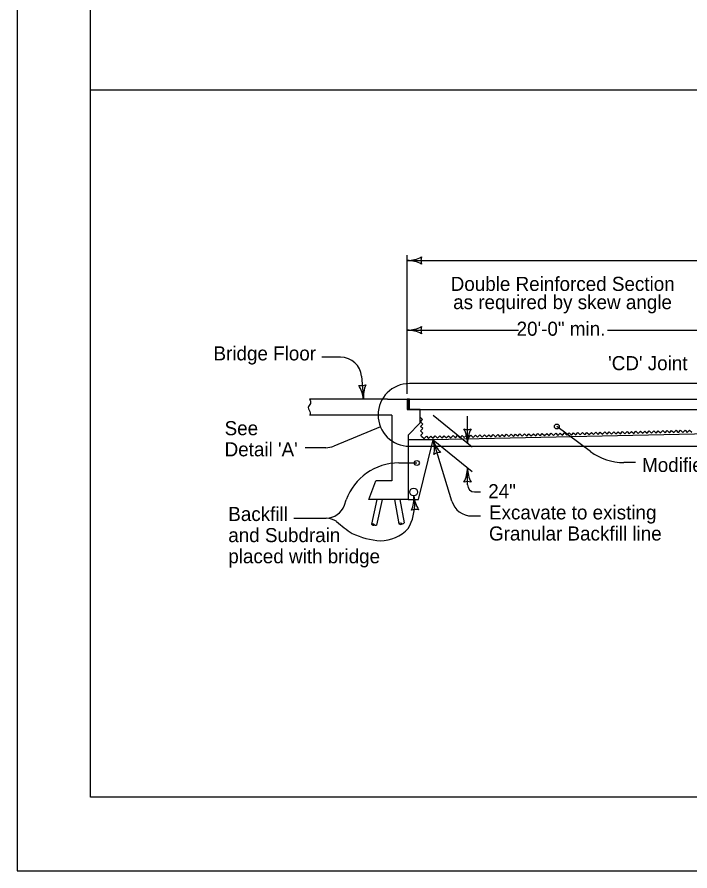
# Model space of a CAD drawing. Extents: x -2135039 to -2120895, y -2139150 to -2136566.
# Drawn here: x -2127839 to -2126883, y -2139150 to -2137937 of the extents above; entities that cross this region are included whole.
import ezdxf

# ---------------------------------------------------------------- set-up
doc = ezdxf.new("R2010")
doc.units = 0
for name, color, linetype in [('dsnDOTLogo', 7, 'Continuous'), ('dsnNonPlotable', 7, 'Continuous'), ('dsnStdDimension', 7, 'Continuous'), ('dsnStdLabel', 7, 'Continuous'), ('dsnStdLineWork', 7, 'Continuous'), ('Level 1', 7, 'Continuous'), ('Level 2', 7, 'Continuous'), ('Level 3', 7, 'Continuous')]:
    doc.layers.add(name, color=color, linetype=linetype)

msp = doc.modelspace()

# ---------------------------------------------------------------- linework, layer by layer
at = {"layer": 'dsnDOTLogo'}
msp.add_lwpolyline([(-2127839, -2139150.4), (-2124495, -2139150.4), (-2124495, -2136566.4), (-2127839, -2136566.4)], close=True, dxfattribs=at)
at = {"layer": 'dsnNonPlotable'}
msp.add_line((-2127734.5, -2138040.9), (-2124599.5, -2138040.9), dxfattribs=at)
at = {"layer": 'dsnStdDimension'}
for p, q in [((-2127248, -2138502.9), (-2127192.8, -2138548)), ((-2127199.2, -2138542.7), (-2127199.2, -2138504.5)), ((-2127248, -2138538.2), (-2127192.8, -2138583.2)), ((-2127199.2, -2138602), (-2127199.2, -2138578)), ((-2127189.2, -2138612), (-2127180.7, -2138612))]:
    msp.add_line(p, q, dxfattribs=at)
for centre, radius, start, end in [((-2127199.2, -2138506.9), 16.5, 252.2666, 287.7333), ((-2127242, -2138542.7), 42.7, 360, 28.0725), ((-2127156.5, -2138542.7), 42.7, 151.9275, 180), ((-2127242, -2138578), 42.7, 331.9275, 360), ((-2127156.5, -2138578), 42.7, 180, 208.0725), ((-2127199.2, -2138613.8), 16.5, 72.2666, 107.7334)]:
    msp.add_arc(centre, radius, start, end, dxfattribs=at)
at = {"layer": 'dsnStdLabel'}
for p, q in [((-2127284.7, -2138472.9), (-2127284.7, -2138275.9)), ((-2127284.7, -2138283.3), (-2126123.4, -2138283.3)), ((-2127284.7, -2138382.3), (-2127126.9, -2138382.3)), ((-2127000.6, -2138382.3), (-2126836.2, -2138382.3)), ((-2127379.4, -2138420.7), (-2127406.1, -2138420.7)), ((-2127349.8, -2138447.8), (-2127347, -2138480.3)), ((-2126476.6, -2138458), (-2127281.7, -2138458)), ((-2127322.9, -2138519.6), (-2127389, -2138547)), ((-2127024.4, -2138554.7), (-2127072.4, -2138519.1)), ((-2127400.4, -2138549.2), (-2127429.6, -2138549.2)), ((-2127281.7, -2138547.1), (-2126476.6, -2138547.1)), ((-2127221.6, -2138625.1), (-2127248, -2138538.2)), ((-2127296.9, -2138570.9), (-2127271.1, -2138570.9)), ((-2126960.4, -2138570.3), (-2126977.2, -2138570.3)), ((-2127374.1, -2138631), (-2127371.4, -2138623.4)), ((-2127193.1, -2138646.2), (-2127180.7, -2138646.2)), ((-2127445.9, -2138649.4), (-2127400.2, -2138649.4))]:
    msp.add_line(p, q, dxfattribs=at)
for centre in [(-2127072.4, -2138519.1), (-2127271.1, -2138570.9)]:
    msp.add_circle(centre, 3.46, dxfattribs=at)
for centre, radius, start, end in [((-2127284.7, -2138240.5), 42.7, 270, 298.0725), ((-2127248.8, -2138283.3), 16.5, 162.2666, 197.7334), ((-2127284.7, -2138326), 42.7, 61.9275, 90), ((-2127284.7, -2138339.5), 42.7, 270, 298.0725), ((-2127248.8, -2138382.3), 16.5, 162.2666, 197.7334), ((-2127284.7, -2138425), 42.7, 61.9275, 90), ((-2127379.4, -2138450.4), 29.7, 4.9696, 90), ((-2127350.1, -2138444.6), 16.5, 257.2356, 292.7023), ((-2127389.6, -2138484), 42.7, 4.969, 33.0415), ((-2127304.4, -2138476.6), 42.7, 156.8965, 184.969), ((-2127281.7, -2138502.6), 44.5, 90, 269.9998), ((-2127400.4, -2138519.5), 29.7, 270, 292.4496), ((-2127207.2, -2138525.8), 42.7, 196.9537, 225.0262), ((-2127288.9, -2138550.7), 42.7, 348.8812, 16.9537), ((-2127207.2, -2138525.8), 42.7, 196.9537, 225.0262), ((-2127288.9, -2138550.7), 42.7, 348.8812, 16.9537), ((-2127237.6, -2138572.5), 16.5, 89.2203, 124.687), ((-2127237.6, -2138572.5), 16.5, 89.2203, 124.687), ((-2126977.2, -2138491.1), 79.2, 233.4243, 270), ((-2127296.9, -2138650.1), 79.2, 90, 160.3012), ((-2127317.8, -2138621.6), 42.5, 337.1139, 5.1864), ((-2127233.1, -2138614), 42.5, 185.1864, 213.2589), ((-2127400.2, -2138621.7), 27.7, 270, 340.3019), ((-2127345.5, -2138629), 71.3, 330.5092, 2.0511), ((-2127193.2, -2138616.5), 29.7, 196.9535, 270), ((-2127272.2, -2138653.3), 16.4, 77.453, 112.9197), ((-2127400.2, -2138677.1), 27.7, 56.8248, 90), ((-2127273.8, -2138534), 163.6, 227.1442, 236.9942), ((-2127323.5, -2138626.4), 55, 270.3325, 316.7198), ((-2127313.9, -2138563.3), 118.5, 245.5915, 265.546)]:
    msp.add_arc(centre, radius, start, end, dxfattribs=at)
at = {"layer": 'dsnStdLineWork'}
for p, q in [((-2127312.9, -2138480.3), (-2127423.5, -2138480.3)), ((-2127312.9, -2138480.3), (-2127284.7, -2138480.3)), ((-2127284.7, -2138480.3), (-2127284.7, -2138495.1)), ((-2127281.7, -2138480.3), (-2127284.7, -2138480.3)), ((-2127284.7, -2138483.7), (-2127281.7, -2138480.7)), ((-2127284.7, -2138481.6), (-2127283.8, -2138480.7)), ((-2127281.7, -2138480.7), (-2127284.7, -2138480.7)), ((-2127284.7, -2138485.8), (-2127281.7, -2138482.8)), ((-2127284.7, -2138487.9), (-2127281.7, -2138484.9)), ((-2127284.7, -2138490), (-2127281.7, -2138487)), ((-2127281.7, -2138480.3), (-2126123.4, -2138480.3)), ((-2127284.7, -2138492.1), (-2127281.7, -2138489.1)), ((-2127284.7, -2138494.2), (-2127281.7, -2138491.2)), ((-2127284.7, -2138495.1), (-2127281.7, -2138495.1)), ((-2127283.5, -2138495.1), (-2127281.7, -2138493.3)), ((-2126123.4, -2138495.2), (-2127281.7, -2138495.2)), ((-2127266.8, -2138495.1), (-2127266.8, -2138514.5)), ((-2127306.9, -2138503.2), (-2127423.5, -2138503.2)), ((-2127306.9, -2138503.2), (-2127306.9, -2138596.1)), ((-2126123.4, -2138512.8), (-2127248, -2138538.2)), ((-2127266.8, -2138514.5), (-2127283.6, -2138531.3)), ((-2127283.6, -2138531.3), (-2127283.6, -2138622.9)), ((-2127248, -2138538.2), (-2127283.6, -2138538.2)), ((-2127268.7, -2138622.9), (-2127248, -2138538.2)), ((-2127339.6, -2138622.9), (-2127329.3, -2138596.1)), ((-2127306.9, -2138596.1), (-2127329.3, -2138596.1)), ((-2127283.6, -2138622.9), (-2127339.6, -2138622.9)), ((-2127328.1, -2138622.9), (-2127335.6, -2138657.7)), ((-2127320.5, -2138622.9), (-2127328.4, -2138659.3)), ((-2127302.9, -2138622.9), (-2127296.6, -2138657.2)), ((-2127295.3, -2138622.9), (-2127289.3, -2138655.9)), ((-2127283.6, -2138622.9), (-2127268.7, -2138622.9))]:
    msp.add_line(p, q, dxfattribs=at)
for points in [[(-2127263.9, -2138533.3), (-2127265.6, -2138531.6), (-2127262.5, -2138528.4), (-2127265.8, -2138525.3), (-2127262.7, -2138522.1), (-2127265.9, -2138519), (-2127262.8, -2138515.7), (-2127266, -2138512.6), (-2127263, -2138509.4), (-2127266.2, -2138506.3), (-2127266, -2138506.1)], [(-2126977.4, -2138527.9), (-2126975.7, -2138529.4), (-2126972.6, -2138526.2), (-2126969.4, -2138529.3), (-2126966.3, -2138526), (-2126963.1, -2138529.1), (-2126960, -2138525.9), (-2126956.7, -2138529), (-2126953.6, -2138525.7), (-2126950.4, -2138528.8), (-2126947.3, -2138525.6), (-2126944.1, -2138528.7), (-2126941, -2138525.4), (-2126937.7, -2138528.5), (-2126934.6, -2138525.3), (-2126931.4, -2138528.4), (-2126928.3, -2138525.1), (-2126925.1, -2138528.2), (-2126922, -2138525), (-2126918.7, -2138528.1), (-2126915.6, -2138524.8), (-2126912.4, -2138527.9), (-2126909.3, -2138524.7), (-2126906.1, -2138527.8), (-2126903, -2138524.5), (-2126901.3, -2138526.1)], [(-2126901.3, -2138526.1), (-2126899.7, -2138527.7), (-2126896.6, -2138524.4), (-2126893.4, -2138527.5), (-2126890.3, -2138524.3), (-2126887.1, -2138527.4), (-2126884, -2138524.1), (-2126880.7, -2138527.2)], [(-2127264.1, -2138533.2), (-2127264, -2138533.1), (-2127260.8, -2138536.2), (-2127257.7, -2138532.9), (-2127254.4, -2138536), (-2127251.4, -2138532.8), (-2127248.1, -2138535.9), (-2127245, -2138532.6), (-2127241.8, -2138535.7), (-2127238.7, -2138532.5), (-2127235.4, -2138535.6), (-2127232.3, -2138532.3), (-2127229.1, -2138535.4), (-2127226, -2138532.2), (-2127222.8, -2138535.3), (-2127219.7, -2138532), (-2127216.4, -2138535.1), (-2127213.3, -2138531.9), (-2127210.1, -2138535), (-2127207, -2138531.8), (-2127205.4, -2138533.3)], [(-2127205.4, -2138533.2), (-2127203.8, -2138534.8), (-2127200.7, -2138531.5), (-2127197.4, -2138534.6), (-2127194.3, -2138531.4), (-2127191.1, -2138534.5), (-2127188, -2138531.2), (-2127184.8, -2138534.3), (-2127181.7, -2138531.1), (-2127178.4, -2138534.2), (-2127175.3, -2138530.9), (-2127172.1, -2138534), (-2127169, -2138530.8), (-2127165.8, -2138533.9), (-2127162.7, -2138530.6), (-2127159.4, -2138533.7), (-2127156.3, -2138530.5), (-2127153.1, -2138533.6), (-2127150, -2138530.3), (-2127146.8, -2138533.4), (-2127143.7, -2138530.2), (-2127140.4, -2138533.3), (-2127137.3, -2138530.1), (-2127134.1, -2138533.1), (-2127131, -2138529.9), (-2127129.4, -2138531.5)], [(-2127129.4, -2138531.4), (-2127127.8, -2138533), (-2127124.7, -2138529.7), (-2127121.4, -2138532.8), (-2127118.3, -2138529.6), (-2127115.1, -2138532.7), (-2127112, -2138529.4), (-2127108.8, -2138532.5), (-2127105.7, -2138529.3), (-2127102.4, -2138532.4), (-2127099.3, -2138529.2), (-2127096.1, -2138532.2), (-2127093, -2138529), (-2127089.8, -2138532.1), (-2127086.7, -2138528.9), (-2127083.4, -2138532), (-2127080.3, -2138528.7), (-2127077.1, -2138531.8), (-2127074, -2138528.6), (-2127070.8, -2138531.7), (-2127067.7, -2138528.4), (-2127064.4, -2138531.5), (-2127061.3, -2138528.3), (-2127058.1, -2138531.4), (-2127055, -2138528.1), (-2127053.4, -2138529.7)], [(-2127053.4, -2138529.7), (-2127051.7, -2138531.2), (-2127048.7, -2138528), (-2127045.4, -2138531.1), (-2127042.3, -2138527.8), (-2127039.1, -2138530.9), (-2127036, -2138527.7), (-2127032.7, -2138530.8), (-2127029.7, -2138527.5), (-2127026.4, -2138530.6), (-2127023.3, -2138527.4), (-2127020.1, -2138530.5), (-2127017, -2138527.2), (-2127013.7, -2138530.3), (-2127010.6, -2138527.1), (-2127007.4, -2138530.2), (-2127004.3, -2138526.9), (-2127001.1, -2138530), (-2126998, -2138526.8), (-2126994.7, -2138529.9), (-2126991.6, -2138526.6), (-2126988.4, -2138529.7), (-2126985.3, -2138526.5), (-2126982.1, -2138529.6), (-2126979, -2138526.3), (-2126977.4, -2138527.9)]]:
    msp.add_lwpolyline(points, dxfattribs=at)
for points in [[(-2127423.5, -2138480.3), (-2127422.3, -2138486.3), (-2127425.3, -2138492.3), (-2127422.5, -2138499.9), (-2127423, -2138503.2)], [(-2127335.6, -2138657.7), (-2127332.6, -2138657.4), (-2127330.8, -2138659.1), (-2127328.4, -2138659.3)], [(-2127335.6, -2138657.7), (-2127333.5, -2138659.2), (-2127331.1, -2138659)], [(-2127296.6, -2138657.2), (-2127293.8, -2138656.1), (-2127291, -2138657.3), (-2127289.3, -2138655.9)], [(-2127296.6, -2138657.2), (-2127293.9, -2138658.1), (-2127291.8, -2138657.3)]]:
    msp.add_spline(points, degree=3, dxfattribs=at)
at = {"layer": 'Level 1'}
msp.add_lwpolyline([(-2127734.5, -2137035.9), (-2124599.5, -2137035.9), (-2124599.5, -2139045.9), (-2127734.5, -2139045.9)], close=True, dxfattribs=at)
at = {"layer": 'Level 2'}
msp.add_circle((-2127275.7, -2138612.2), 5.57, dxfattribs=at)
msp.add_arc((-2127189.2, -2138602), 10, 180, 270, dxfattribs=at)
at = {"layer": 'Level 3'}
for p, q in [((-2127281.7, -2138495.1), (-2127281.7, -2138480.3)), ((-2127281.7, -2138480.3), (-2126836.2, -2138480.3)), ((-2127281.7, -2138495.1), (-2127281.7, -2138480.3)), ((-2127266.4, -2138495.1), (-2127281.7, -2138495.1)), ((-2127244.6, -2138495.2), (-2127266.4, -2138495.1)), ((-2126836.2, -2138495.2), (-2127244.6, -2138495.2))]:
    msp.add_line(p, q, dxfattribs=at)

# ---------------------------------------------------------------- texts
at = {"layer": 'dsnStdDimension'}
msp.add_text('24"', height=20, dxfattribs=at).set_placement((-2127169.8, -2138621))
at = {"layer": 'dsnStdLabel'}
for s, p in [('Double Reinforced Section', (-2127223.1, -2138326.5)), ('as required by skew angle', (-2127219.6, -2138352.4)), ('20\'-0" min.', (-2127129.5, -2138390.2)), ('Bridge Floor', (-2127560, -2138425.2)), ("'CD' Joint", (-2126999.5, -2138439.1)), ('See', (-2127544.2, -2138531.5)), ("Detail 'A'", (-2127544.2, -2138561.5)), ('Modified Subbase', (-2126951.3, -2138583.7)), ('Backfill', (-2127539, -2138653.4)), ('Excavate to existing', (-2127168.7, -2138651.1)), ('and Subdrain', (-2127539, -2138683.4)), ('Granular Backfill line', (-2127168.7, -2138681.1)), ('placed with bridge', (-2127539, -2138713.4))]:
    msp.add_text(s, height=20, dxfattribs=at).set_placement(p)

doc.saveas('drawing.dxf')
